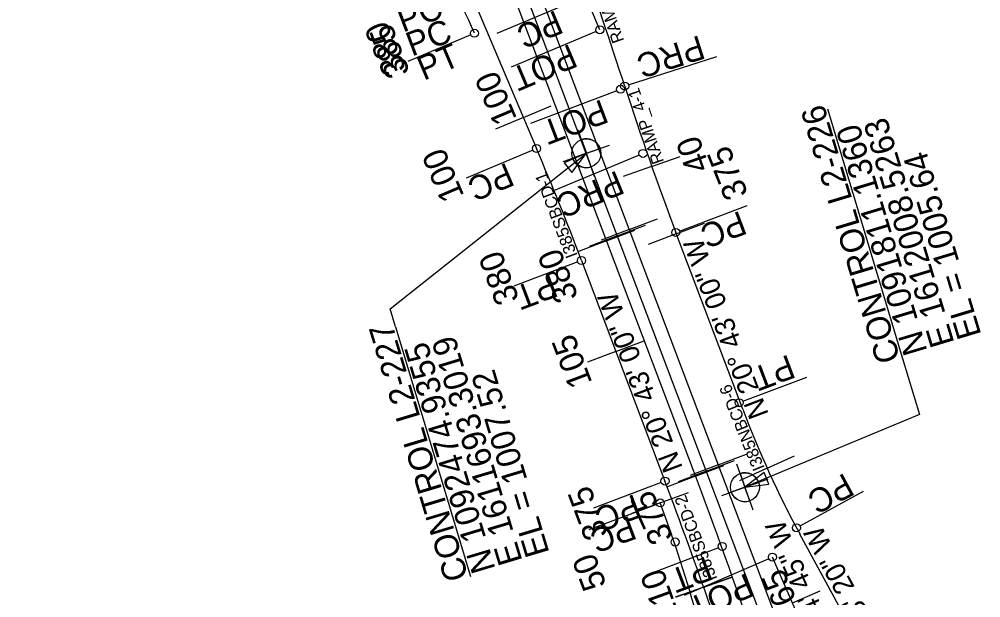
# Model space of a CAD drawing. Extents: x 1603447 to 1622636, y 1083818 to 1103958.
# Drawn here: x 1610566 to 1612477, y 1091591 to 1092741 of the extents above; entities that cross this region are included whole.
import ezdxf

# ---------------------------------------------------------------- set-up
doc = ezdxf.new("R2010")
doc.units = 0
for name, color, linetype in [('Level 1', 7, 'Continuous'), ('RD_HC_Points', 7, 'Continuous'), ('RD_HC_SUR_Bearing_TX400', 7, 'Continuous'), ('RD_HC_SUR_CL400', 7, 'Continuous'), ('RD_HC_SUR_PC_PT_400', 7, 'Continuous'), ('RD_HC_SUR_Tic400', 7, 'Continuous'), ('RD_HC_SUR_TX_Sta400', 7, 'Continuous'), ('RD_SHT_Misc1', 7, 'Continuous'), ('RD_TX_Misc1', 7, 'Continuous')]:
    doc.layers.add(name, color=color, linetype=linetype)

msp = doc.modelspace()

# ---------------------------------------------------------------- linework, layer by layer
at = {"layer": 'RD_HC_Points'}
for p, q in [((1612172.4, 1092563), (1612321.6, 1092066.9)), ((1611314, 1092129.6), (1611463.3, 1091633.6))]:
    msp.add_line(p, q, dxfattribs=at)
for points in [[(1611314, 1092129.6), (1611303.2, 1092165.5), (1611693.3, 1092474.9)], [(1612321.6, 1092066.9), (1612355.1, 1091955.8), (1612008.5, 1091811.1)]]:
    msp.add_lwpolyline(points, dxfattribs=at)
for points in [[(1611664.7, 1092436.4), (1611693.3, 1092474.9), (1611649.3, 1092455.9)], [(1612046.5, 1091840.5), (1612008.5, 1091811.1), (1612056.1, 1091817.5)]]:
    msp.add_lwpolyline(points, close=True, dxfattribs=at)
at = {"layer": 'RD_HC_SUR_CL400'}
for p, q in [((1611451.4, 1092821.2), (1611594.4, 1092484.4)), ((1611906.2, 1091844.6), (1611542.3, 1092806.5)), ((1612051.1, 1091527.2), (1611564.1, 1092814.8)), ((1612071.1, 1091550.5), (1611593.4, 1092813.6)), ((1611720.1, 1092720.3), (1611691.7, 1092787.4)), ((1612004, 1091966.2), (1611871.1, 1092317.5)), ((1611683.7, 1092261.8), (1611849.6, 1091823.2)), ((1612283.8, 1091412.9), (1612117.9, 1091717.6)), ((1612191.2, 1091378.6), (1612063.1, 1091672.2))]:
    msp.add_line(p, q, dxfattribs=at)
for centre, radius, start, end in [((1604151.3, 1090166.4), 8000, 17.77323, 21.73435), ((1610771.5, 1092416.4), 760, 23.0073, 58.635), ((1617483.2, 1094439.9), 6000, 197.77323, 200.71665), ((1606071.6, 1090139.3), 6000, 20.71665, 23.00726), ((1613874.7, 1092673.7), 2000, 200.7167, 208.5554), ((1613190, 1096417.9), 5729.6, 232.02562, 245.46665), ((1602552.7, 1088307.1), 10000, 16.52176, 20.71665), ((1602552.7, 1088307.1), 9939.5, 19.19672, 20.71665), ((1609311.2, 1090834.2), 2700, 10.058, 20.5018)]:
    msp.add_arc(centre, radius, start, end, dxfattribs=at)
at = {"layer": 'RD_HC_SUR_PC_PT_400'}
for p, q in [((1611684.4, 1092784.3), (1611515.4, 1092712.9)), ((1611463.7, 1092710.3), (1611338.6, 1092657.2)), ((1611712.7, 1092717.2), (1611543.8, 1092645.8)), ((1611777.1, 1092610.9), (1611952.8, 1092667.2)), ((1611753.9, 1092599.2), (1611582.3, 1092534.4)), ((1611587, 1092481.3), (1611454.7, 1092425.1)), ((1611798.5, 1092471.4), (1611628.3, 1092400.4)), ((1611878.6, 1092320.3), (1612013.1, 1092371.2)), ((1611676.2, 1092259), (1611549.1, 1092210.9)), ((1612004.4, 1091981.9), (1612131.5, 1092029.9)), ((1611842.1, 1091820.3), (1611707.6, 1091769.5)), ((1612118, 1091734.3), (1612244.2, 1091803.1)), ((1611832.7, 1091777.1), (1611698.1, 1091726.7)), ((1611955.8, 1091690.7), (1611828.8, 1091642.6)), ((1612055.7, 1091669), (1611887.7, 1091595.6))]:
    msp.add_line(p, q, dxfattribs=at)
for centre in [(1611720.1, 1092720.3), (1611471, 1092713.5), (1611769.5, 1092608.4), (1611761.3, 1092602.1), (1611594.4, 1092484.4), (1611805.9, 1092474.5), (1611871.1, 1092317.5), (1611683.7, 1092261.8), (1611997, 1091979), (1611849.6, 1091823.2), (1611840.2, 1091779.9), (1612110.9, 1091730.5), (1611869.7, 1091702.2), (1611963.3, 1091693.5), (1612063.1, 1091672.2)]:
    msp.add_circle(centre, 8, dxfattribs=at)
at = {"layer": 'RD_HC_SUR_Tic400'}
for p, q in [((1611490, 1092730.1), (1611490, 1092730.1)), ((1611490, 1092730.1), (1611490, 1092730.1)), ((1611728.3, 1092733.5), (1611728.3, 1092733.5)), ((1611637.2, 1092697.7), (1611637.2, 1092697.7)), ((1611592.1, 1092675), (1611592.1, 1092675)), ((1611613.3, 1092684.7), (1611613.3, 1092684.7)), ((1611529.1, 1092638.1), (1611529.1, 1092638.1)), ((1611529.1, 1092638.1), (1611529.1, 1092638.1)), ((1611759.8, 1092638.6), (1611759.8, 1092638.6)), ((1611672.6, 1092604.2), (1611672.6, 1092604.2)), ((1611627.5, 1092581.4), (1611627.5, 1092581.4)), ((1611648.7, 1092591.1), (1611648.7, 1092591.1)), ((1611568.2, 1092546), (1611623.4, 1092569.5)), ((1611568.2, 1092546), (1611623.4, 1092569.5)), ((1611568.2, 1092546), (1611513, 1092522.6)), ((1611568.2, 1092546), (1611513, 1092522.6)), ((1611790.8, 1092543.5), (1611790.8, 1092543.5)), ((1611708, 1092510.7), (1611708, 1092510.7)), ((1611662.9, 1092487.9), (1611662.9, 1092487.9)), ((1611684, 1092497.6), (1611684, 1092497.6)), ((1611823.1, 1092448.9), (1611879.7, 1092468.8)), ((1611607.2, 1092454), (1611607.2, 1092454)), ((1611823.1, 1092448.9), (1611766.5, 1092429)), ((1611719.4, 1092404.1), (1611719.4, 1092404.1)), ((1611743.3, 1092417.1), (1611743.3, 1092417.1)), ((1611698.2, 1092394.4), (1611698.2, 1092394.4)), ((1611645, 1092361.4), (1611645, 1092361.4)), ((1611857.1, 1092354.8), (1611857.1, 1092354.8)), ((1611754.8, 1092310.5), (1611810.9, 1092331.8)), ((1611778.7, 1092323.6), (1611834.8, 1092344.8)), ((1611872.1, 1092314.9), (1611928.2, 1092336.2)), ((1611754.8, 1092310.5), (1611698.7, 1092289.3)), ((1611778.7, 1092323.6), (1611722.6, 1092302.4)), ((1611733.6, 1092300.8), (1611789.7, 1092322.1)), ((1611872.1, 1092314.9), (1611815.9, 1092293.7)), ((1611733.6, 1092300.8), (1611677.5, 1092279.6)), ((1611681.3, 1092268.2), (1611681.3, 1092268.2)), ((1611681.3, 1092268.2), (1611681.3, 1092268.2)), ((1611790.2, 1092217), (1611790.2, 1092217)), ((1611814.1, 1092230.1), (1611814.1, 1092230.1)), ((1611907.4, 1092221.4), (1611907.4, 1092221.4)), ((1611769, 1092207.3), (1611769, 1092207.3)), ((1611716.6, 1092174.7), (1611716.6, 1092174.7)), ((1611849.5, 1092136.5), (1611849.5, 1092136.5)), ((1611825.5, 1092123.5), (1611825.5, 1092123.5)), ((1611942.8, 1092127.9), (1611942.8, 1092127.9)), ((1611752, 1092081.1), (1611808.1, 1092102.4)), ((1611752, 1092081.1), (1611808.1, 1092102.4)), ((1611804.4, 1092113.8), (1611804.4, 1092113.8)), ((1611752, 1092081.1), (1611695.9, 1092059.9)), ((1611752, 1092081.1), (1611695.9, 1092059.9)), ((1611884.8, 1092043), (1611884.8, 1092043)), ((1611839.7, 1092020.2), (1611839.7, 1092020.2)), ((1611860.9, 1092029.9), (1611860.9, 1092029.9)), ((1611978.2, 1092034.3), (1611978.2, 1092034.3)), ((1611787.4, 1091987.6), (1611787.4, 1091987.6)), ((1611920.2, 1091949.5), (1611920.2, 1091949.5)), ((1611875.1, 1091926.7), (1611875.1, 1091926.7)), ((1611896.3, 1091936.4), (1611896.3, 1091936.4)), ((1612013.7, 1091940.9), (1612013.7, 1091940.9)), ((1611822.8, 1091894.1), (1611822.8, 1091894.1)), ((1611955.6, 1091855.9), (1612011.7, 1091877.1)), ((1612052.7, 1091848.8), (1612107.3, 1091873.5)), ((1611955.6, 1091855.9), (1611899.5, 1091834.7)), ((1611910.5, 1091833.2), (1611966.6, 1091854.3)), ((1611931.7, 1091842.9), (1611987.8, 1091864.1)), ((1612052.7, 1091848.8), (1611998, 1091824)), ((1611910.5, 1091833.2), (1611854.3, 1091812)), ((1611931.7, 1091842.9), (1611875.5, 1091821.7)), ((1611840.2, 1091779.9), (1611896.4, 1091800.9)), ((1611858.1, 1091800.5), (1611858.1, 1091800.5)), ((1611840.2, 1091779.9), (1611784, 1091758.9)), ((1611991, 1091762.4), (1611991, 1091762.4)), ((1612096.2, 1091758.7), (1612096.2, 1091758.7)), ((1611945.3, 1091739.4), (1611945.3, 1091739.4)), ((1611967, 1091749.3), (1611967, 1091749.3)), ((1611892.8, 1091706.7), (1611892.8, 1091706.7)), ((1611893.5, 1091707), (1611893.5, 1091707)), ((1611873.5, 1091685.6), (1611873.5, 1091685.6)), ((1612026.3, 1091668.9), (1612026.3, 1091668.9)), ((1612143.5, 1091670.7), (1612143.5, 1091670.7)), ((1611979.1, 1091645.3), (1611979.1, 1091645.3)), ((1612002.4, 1091655.8), (1612002.4, 1091655.8)), ((1611926.5, 1091612.6), (1611983.1, 1091632.5)), ((1611928.1, 1091613.2), (1611984.6, 1091633.4)), ((1611926.5, 1091612.6), (1611869.9, 1091592.6)), ((1611928.1, 1091613.2), (1611871.6, 1091592.9)), ((1611901.9, 1091607.6), (1611901.9, 1091607.6)), ((1612102.7, 1091581.4), (1612157.7, 1091605.4))]:
    msp.add_line(p, q, dxfattribs=at)
at = {"layer": 'RD_SHT_Misc1'}
for p, q in [((1611709.6, 1092429), (1611677, 1092520.9)), ((1611683.7, 1092502), (1611693.3, 1092474.9)), ((1611647.4, 1092458.6), (1611739.2, 1092491.3)), ((1611693.3, 1092474.9), (1611720.4, 1092484.6)), ((1611693.3, 1092474.9), (1611666.2, 1092465.3)), ((1611702.9, 1092447.8), (1611693.3, 1092474.9)), ((1612024.9, 1091765.2), (1611992.2, 1091857.1)), ((1611998.9, 1091838.2), (1612008.5, 1091811.1)), ((1611962.6, 1091794.8), (1612054.5, 1091827.5)), ((1612008.5, 1091811.1), (1611981.4, 1091801.5)), ((1612008.5, 1091811.1), (1612035.6, 1091820.8)), ((1612018.2, 1091784), (1612008.5, 1091811.1))]:
    msp.add_line(p, q, dxfattribs=at)
for centre in [(1611693.3, 1092474.9), (1612008.5, 1091811.1)]:
    msp.add_circle(centre, 28.8, dxfattribs=at)
for centre, start, end in [((1611693.3, 1092474.9), 19.573, 109.573), ((1611693.3, 1092474.9), 199.573, 289.573), ((1612008.5, 1091811.1), 19.573, 109.573), ((1612008.5, 1091811.1), 199.573, 289.573)]:
    msp.add_arc(centre, 28.8, start, end, dxfattribs=at)

# ---------------------------------------------------------------- texts
at = {"layer": 'Level 1'}
for s, rotation, p in [('385', 110.7167, (1611343.3, 1092635.5)), ('375', 111.6308, (1612015.5, 1092394)), ('105', 110.7167, (1611705.6, 1092019)), ('375', 110.7167, (1611737.5, 1091717.3)), ('375', 114.3583, (1611866.9, 1091711.1)), ('65', 113.5791, (1612112.1, 1091587.3))]:
    msp.add_text(s, height=48, rotation=rotation, dxfattribs=at).set_placement(p)
at = {"layer": 'RD_HC_Points'}
for s, p in [('CONTROL L2-226', (1612317.8, 1092065.8)), ('E 1612008.5263', (1612425.1, 1092098)), ('N 1091811.1360', (1612371.4, 1092081.9)), ('EL = 1005.64', (1612478.7, 1092114.2)), ('CONTROL L2-227', (1611459.5, 1091632.5)), ('N 1092474.9355', (1611513.1, 1091648.6)), ('E 1611693.3019', (1611566.7, 1091664.7)), ('EL = 1007.52', (1611620.3, 1091680.9))]:
    msp.add_text(s, height=48, rotation=106.7478, dxfattribs=at).set_placement(p)
at = {"layer": 'RD_HC_SUR_Bearing_TX400'}
for s, rotation, p in [('N 20%%d 43\' 00" W', 110.7167, (1612056.1, 1091956.3)), ('N 20%%d 43\' 00" W', 110.7167, (1611885.4, 1091849.9)), ('N 23%%d 34\' 45" W', 113.5791, (1612235.5, 1091403.8)), ('N 28%%d 33\' 20" W', 118.5554, (1612339.3, 1091406.9))]:
    msp.add_text(s, height=40, rotation=rotation, dxfattribs=at).set_placement(p)
at = {"layer": 'RD_HC_SUR_PC_PT_400'}
for s, rotation, p in [('PC', 20.7167, (1611328.8, 1092714.5)), ('PC', 202.9196, (1611632.6, 1092760.2)), ('PC', 20.7167, (1611346.5, 1092667)), ('PRC', 197.7732, (1611918.4, 1092710.2)), ('PT', 23.0073, (1611370.2, 1092618.8)), ('POT', 202.9196, (1611661, 1092693.2)), ('POT', 200.7167, (1611724.1, 1092582.9)), ('PC', 203.0073, (1611535.3, 1092457.2)), ('PRC', 202.6537, (1611754.4, 1092441.4)), ('PC', 200.7167, (1611999.1, 1092361.3)), ('PT', 200.7167, (1611623.6, 1092236.9)), ('PT', 200.7167, (1612095.5, 1092075.6)), ('PC', 208.5554, (1612206.9, 1091840.5)), ('PC', 200.7167, (1611789.5, 1091798.3)), ('PC', 200.5018, (1611780, 1091755.2)), ('PT', 200.7167, (1611931.5, 1091674.2)), ('POT', 203.5791, (1612011.9, 1091641.2))]:
    msp.add_text(s, height=48, rotation=rotation, dxfattribs=at).set_placement(p)
at = {"layer": 'RD_HC_SUR_TX_Sta400'}
for s, rotation, p in [('380', 112.9196, (1611336.6, 1092642.6)), ('100', 113.0073, (1611556.1, 1092543.7)), ('40', 109.1313, (1611939.1, 1092445.8)), ('100', 113.0073, (1611451.2, 1092390.5)), ('380', 110.7167, (1611560.7, 1092184.7)), ('380', 110.7167, (1611678, 1092189.1)), ('50', 110.7167, (1611734, 1091616.7)), ('110', 109.7189, (1611880.7, 1091551.9))]:
    msp.add_text(s, height=48, rotation=rotation, dxfattribs=at).set_placement(p)
at = {"layer": 'RD_TX_Misc1'}
for s, rotation, p in [('RAMP_4-2', 108.9307, (1611768.7, 1092698.7)), ('RAMP_4-1', 108.826, (1611848, 1092458.3)), ('I385SBCD-1', 110.7264, (1611676.4, 1092271.9)), ('I385NBCD-6', 112.3399, (1612048.2, 1091849.7)), ('I385SBCD-2', 110.7496, (1611954.1, 1091629.1))]:
    msp.add_text(s, height=24, rotation=rotation, dxfattribs=at).set_placement(p)

doc.saveas('drawing.dxf')
